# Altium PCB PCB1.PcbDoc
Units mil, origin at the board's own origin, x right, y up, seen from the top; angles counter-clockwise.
Board outline 3900 x 3400 mil, 2 copper layers (Top Layer, Bottom Layer); 10 components, 22 nets, 98 pads, 56 vias.
Unrouted connection lines stored in the file: 22.
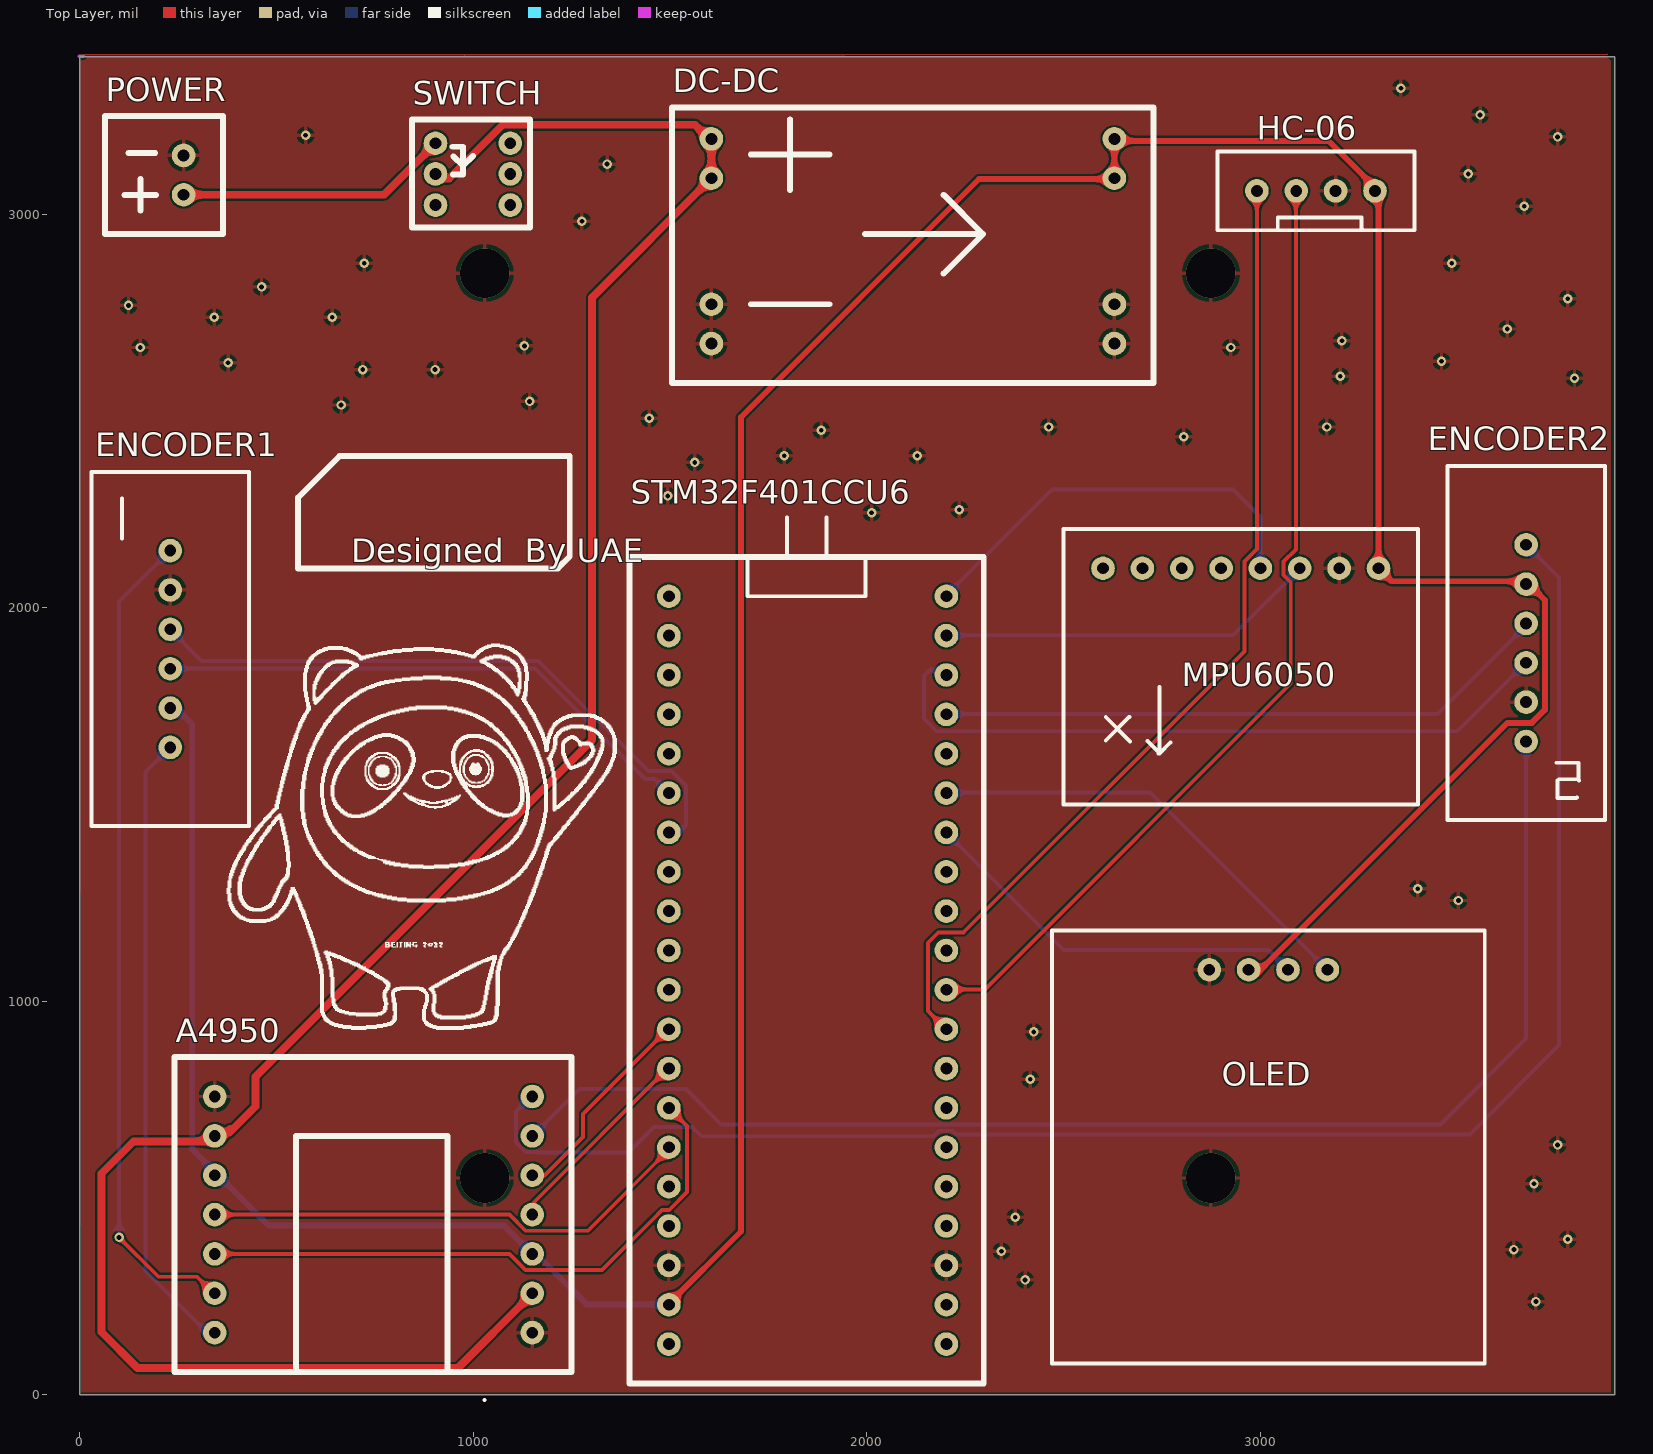
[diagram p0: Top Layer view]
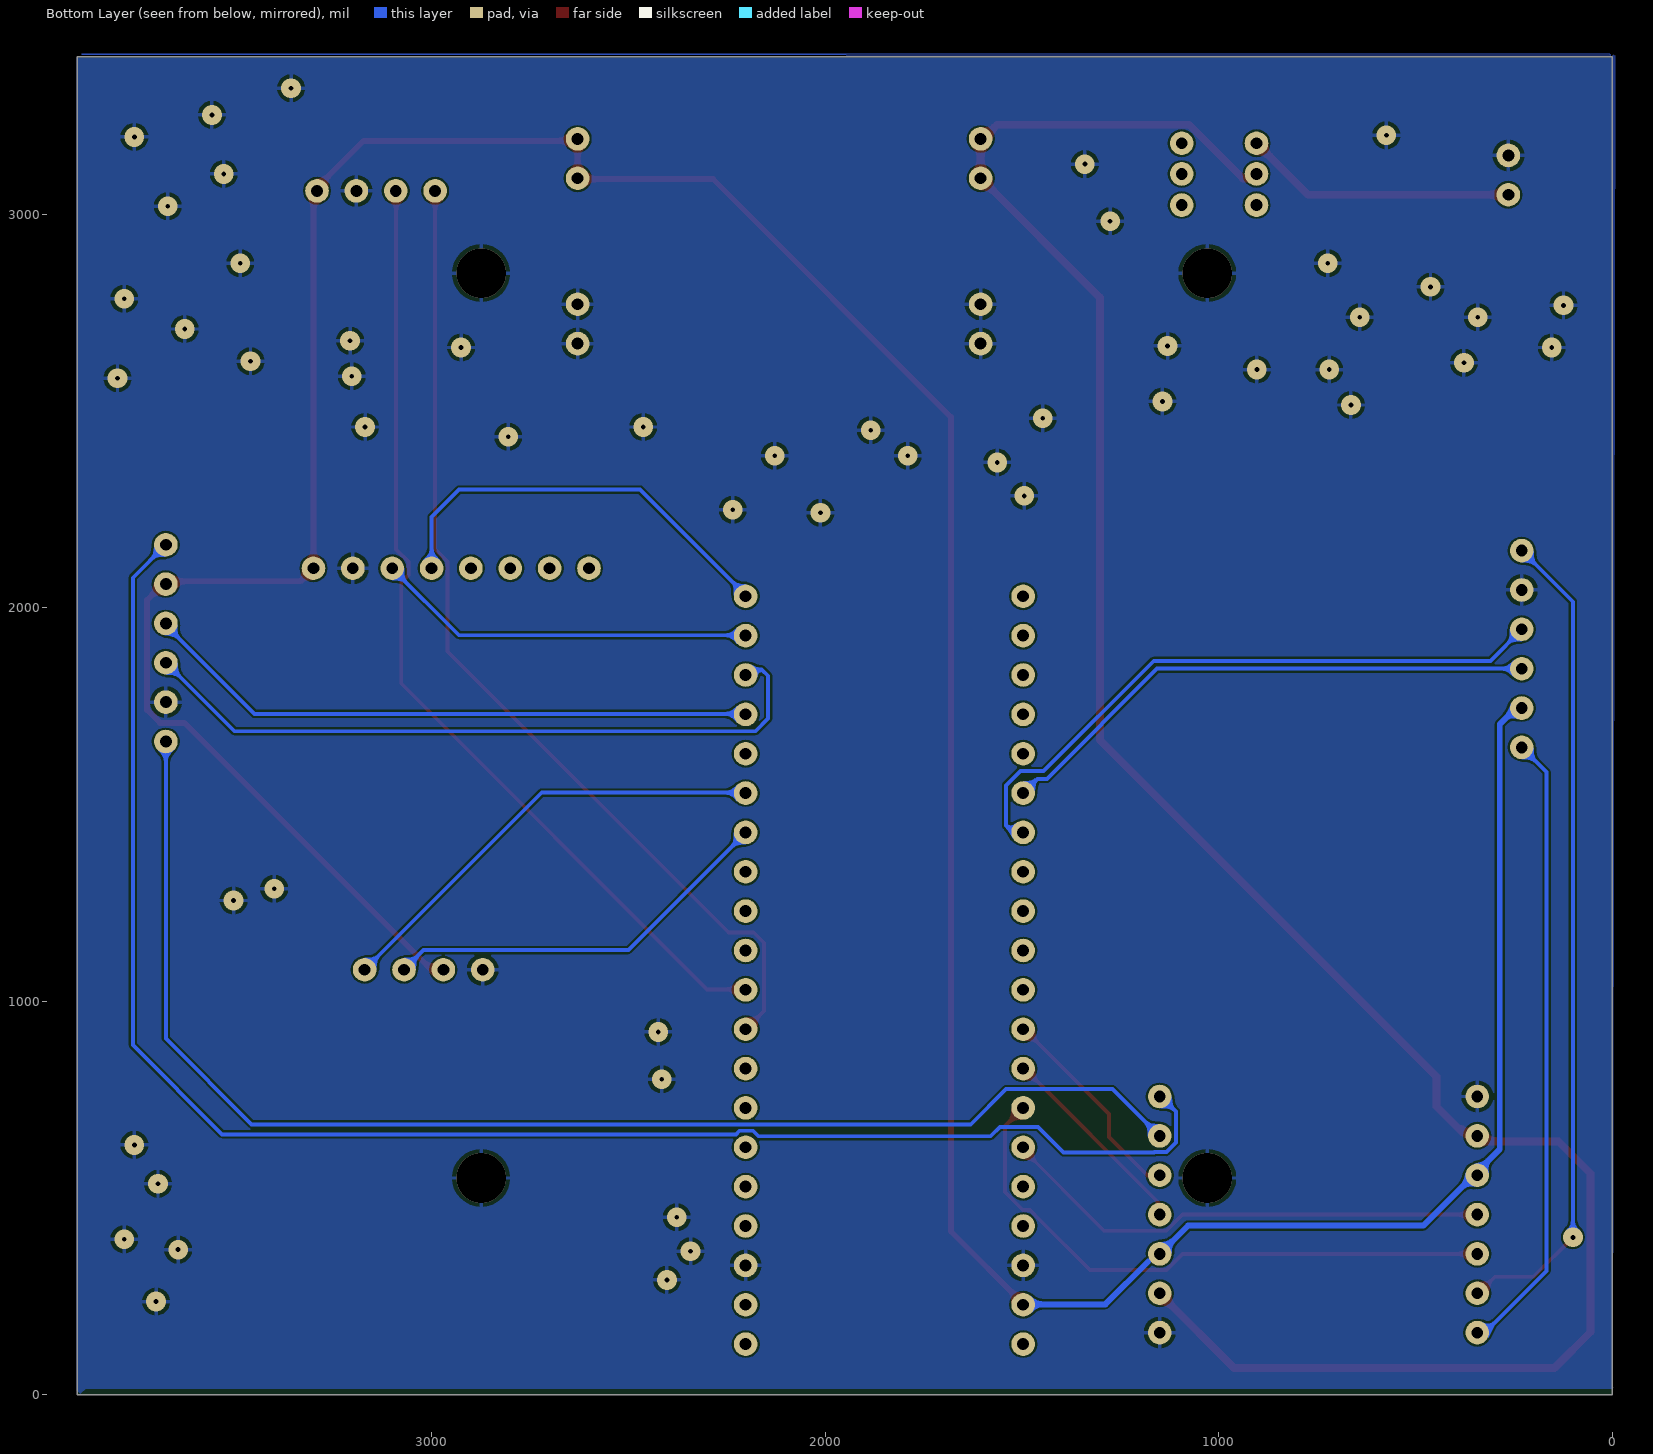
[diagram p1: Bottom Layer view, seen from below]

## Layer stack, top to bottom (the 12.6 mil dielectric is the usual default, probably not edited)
Top Solder: solder mask 0.4, Solder Resist, Dk 3.5
Top Layer: signal copper 1.4
Dielectric 1: dielectric 12.6, FR-4, Dk 4.8
Bottom Layer: signal copper 1.4
Bottom Solder: solder mask 0.4, Solder Resist, Dk 3.5

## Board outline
0,0 3900,0 3900,3400 0,3400

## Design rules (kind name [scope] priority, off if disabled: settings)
Clearance [All] p1: gap=6 ignorepadtopadclearanceinfootprint=FALSE except(5: Arc-Poly Track-Poly SMDPad-Poly THPad-Poly Via-Poly Fill-Poly Poly-Poly)
HoleSize [All] p1: absolutevalues=TRUE maxlimit=150 minlimit=1 maxpercent=80.000 minpercent=20.000
PolygonConnect [All] p1: connectstyle=Relief reliefconductorwidth=10 reliefentries=4 polygonreliefangle="90 Angle" airgapwidth=10
RoutingVias [All] p1: holewidth=12 width=24 viastyle="Through Hole" minholewidth=12 minwidth=10 maxholewidth=135 maxwidth=150
SilkToSolderMaskClearance [IsPad] p1: minsilkscreentomaskgap=4.9 clearancetoexposedcopper=TRUE
SolderMaskExpansion [All] p1: expansion=4
Width Width_3 [InNet('12V-IN')] p1: maxlimit=20 minlimit=10 preferedwidth=20
Width Width_1 [(InNet('12V') OR InNet('12V IN'))] p2: maxlimit=20 minlimit=10 preferedwidth=20
Width Width_2 [InNet('5V')] p3: maxlimit=15 minlimit=10 preferedwidth=15
Width [All] p4: maxlimit=10 minlimit=10 preferedwidth=10
28 further rules are at their usual default settings.

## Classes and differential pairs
component class Sheet1: DC-DC ENCODER1 ENCODER2 HC-06 MPU6050 OLED POWER STM32F401CCU6 SWITCH

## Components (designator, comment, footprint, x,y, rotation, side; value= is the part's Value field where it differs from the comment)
A4950 "A4950" A4950 1150,758 r180 top
DC-DC "DC-DC" DC-DC 1605,2671 r0 top
ENCODER1 "ENCODER1" ENCODER1 230,2145 r0 top
ENCODER2 "ENCODER2" ENCODER2 3675,1660 r180 top
HC-06 "HC-06" HC-06 2991,3059 r270 top
MPU6050 "MPU6050" MPU6050 3300,2100 r270 top
OLED "OLED" OLED 2870,1080 r0 top
POWER "POWER" POWER 264,3149 r0 top
STM32F401CCU6 "STM32F401CCU6" STM32F401CCU6 1497,129 r0 top
SWITCH "SWITCH" SIWITCH 994,3180 r0 top

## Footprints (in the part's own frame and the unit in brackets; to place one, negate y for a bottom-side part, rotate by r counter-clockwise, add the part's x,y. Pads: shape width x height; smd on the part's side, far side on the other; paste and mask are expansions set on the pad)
A4950 [mil]
  round 60 hole 30: 1(0,600) 2(0,500) 3(0,400) 4(0,300) 5(0,200) 6(0,100) 7(0,0) 8(807,600) 9(807,500) 10(807,400) 11(807,300) 12(807,200) 13(807,100) 14(807,0)
  silkscreen extent -100,-100 909,700
DC-DC [mil]
  round 60 hole 30: 1(0,0) 2(0,100) 3(0,420) 4(0,520) 5(1024,0) 6(1024,100) 7(1024,420) 8(1024,520)
  silkscreen extent -100,-100 1123,600
ENCODER1 [mil]
  round 60 hole 30: 1(0,0) 2(0,-100) 3(0,-200) 4(0,-300) 5(0,-400) 6(0,-500)
  silkscreen extent -200,-700 200,200
ENCODER2 [mil]
  round 60 hole 30: 1(0,0) 2(0,-100) 3(0,-200) 4(0,-300) 5(0,-400) 6(0,-500)
  silkscreen extent -200,-700 200,200
HC-06 [mil]
  round 60 hole 30: 1(0,0) 2(0,100) 3(0,200) 4(0,300)
  silkscreen extent -100,-100 100,400
MPU6050 [mil]
  round 60 hole 30: 1(0,0) 2(0,-100) 3(0,-200) 4(0,-300) 5(0,-400) 6(0,-500) 7(0,-600) 8(0,-700)
  silkscreen extent -100,-800 600,100
OLED [mil]
  round 60 hole 30: 1(0,0) 2(100,0) 3(200,0) 4(300,0)
  silkscreen extent -400,-1000 700,100
POWER [mil]
  round 60 hole 30: 1(0,0) 2(0,-100)
  silkscreen extent -200,-200 100,100
SIWITCH [mil]
  round 60 hole 30: 1(-90,0) 2(-90,-78) 3(-90,-157) 4(100,0) 5(100,-78) 6(100,-157)
  silkscreen extent -150,-214 150,60
STM32F401CCU6 [mil]
  round 60 hole 30: 1(0,1900) 2(0,1800) 3(0,1700) 4(0,1600) 5(0,1500) 6(0,1400) 7(0,1300) 8(0,1200) 9(0,1100) 10(0,1000) 11(0,900) 12(0,800) 13(0,700) 14(0,600) 15(0,500) 16(0,400) 17(0,300) 18(0,200) 19(0,100) 20(0,0) 21(705,1900) 22(705,1800) 23(705,1700) 24(705,1600) 25(705,1500) 26(705,1400) 27(705,1300) 28(705,1200) 29(705,1100) 30(705,1000) 31(705,900) 32(705,800) 33(705,700) 34(705,600) 35(705,500) 36(705,400) 37(705,300) 38(705,200) 39(705,100) 40(705,0)
  silkscreen extent -100,-100 800,2100

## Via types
v1: diameter 24/50 (per signal layer), hole 12, Top Layer to Bottom Layer, 52 vias
v2: diameter 126, hole 126, Top Layer to Bottom Layer, 4 vias

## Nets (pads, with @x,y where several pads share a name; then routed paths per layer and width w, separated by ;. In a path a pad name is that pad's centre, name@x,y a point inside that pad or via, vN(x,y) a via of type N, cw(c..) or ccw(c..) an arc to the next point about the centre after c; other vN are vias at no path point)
5V: A4950.3 A4950.12 DC-DC.7 DC-DC.8 ENCODER1.5 ENCODER2.5 HC-06.4 MPU6050.1 OLED.2 STM32F401CCU6.19 | length 9562.8
  Top Layer w15: STM32F401CCU6.19@1495,230 1680,415 1680,2484 2285,3089 2621,3089 DC-DC.7@2627,3083 ; DC-DC.7 DC-DC.8@2629,3186 ; DC-DC.8 DC-DC.8@2629,3186 ; OLED.2 3000,1080 3627.5,1707.5 3689.68,1707.5 3722.5,1740.32 3722.5,2019.68 3675,2067.18 3332.82,2067.18 MPU6050.1 3300,3059 3173,3186 DC-DC.8@2629,3186
  Bottom Layer w15: ENCODER1.5 245,1745 286,1704 286,624 480,430 1078,430 A4950.3 ; 1179,339 1288,230 STM32F401CCU6.19@1495,230
12V: A4950.2 A4950.13 DC-DC.3 DC-DC.4 SWITCH.2 | length 5788.4
  Top Layer w20: 380,666 447,733 447,809 1302,1664 1302,2788 DC-DC.3 DC-DC.4 ; 384,676 352,644 137,644 55,562 55,160 147,68 961,68 A4950.2@1143.5,250.5 ; SWITCH.2@895,3100 905.05,3089.95 937.95,3089.95 1075,3227 1563,3227 DC-DC.4@1596,3194
12V-IN: POWER.2 SWITCH.1 | length 694.3
  Top Layer w20: POWER.2 773,3049 SWITCH.1
AIN1: A4950.5 STM32F401CCU6.12 | length 503.1
  Top Layer w10: 1181,557 1279,655 1279,714 STM32F401CCU6.12@1495,930
AIN2: A4950.4 STM32F401CCU6.13 | length 524.4
  Top Layer w10: A4950.4@1144,451 1144,460 1153,469 1153,488 STM32F401CCU6.13@1495,830
AOUT1: A4950.9 ENCODER1.1 | length 2115.1
  Top Layer w10: v1(100,400) 200,300 298,300 329,269 A4950.9@362,269
  Bottom Layer w10: v1(100,400) 100,2015 ENCODER1.1
AOUT2: A4950.8 ENCODER1.6 | length 1587.5
  Bottom Layer w10: ENCODER1.6 167,1582 167,315 325,157 A4950.8@333,157
BIN1: A4950.10 STM32F401CCU6.14 | length 1548.1
  Top Layer w10: A4950.10 1092.02,358 1133.02,317 1327.02,317 1456,445.98 1480.02,470 1498,470 1543,515 1543,683 STM32F401CCU6.14 STM32F401CCU6.14@1513,729
BIN2: A4950.11 STM32F401CCU6.15 | length 1270.8
  Top Layer w10: A4950.11 1092.02,458 1133.02,417 1291,417 1503,629 STM32F401CCU6.15
BOUT1: A4950.6 ENCODER2.1 | length 3450.7
  Bottom Layer w10: A4950.6@1152,668 1161,668 1270,777 1540,777 1630,687 3457,687 3675,905 ENCODER2.1
BOUT2: A4950.7 ENCODER2.6 | length 4218.1
  Bottom Layer w10: A4950.7@1132,743 1109,720 1109,641.02 1133.02,617 1163,617 1164,616 1394,616 1459,681 1555.98,681 1579.98,657 2169.02,657 2183.02,671 2217.98,671 2226.98,662 3532,662 3759,889 3759,2076 ENCODER2.6
EN1A: ENCODER1.4 STM32F401CCU6.6 | length 1397.9
  Bottom Layer w10: ENCODER1.4 1156.72,1845 1436.72,1565 1461,1565 STM32F401CCU6.6
EN1B: ENCODER1.3 STM32F401CCU6.7 | length 1637
  Bottom Layer w10: ENCODER1.3 310,1865 1165,1865 1445,1585 1503.64,1585 1540,1548.64 1540,1446 1513,1419 STM32F401CCU6.7@1491,1419
EN2A: ENCODER2.4 STM32F401CCU6.24 | length 1573.2
  Bottom Layer w10: STM32F401CCU6.24@2200,1730 3450,1730 3675,1955 ENCODER2.4
EN2B: ENCODER2.3 STM32F401CCU6.23 | length 1790.5
  Bottom Layer w10: STM32F401CCU6.23@2200,1830 2188,1842 2160,1842 2145,1827 2145,1718 2177,1686 3501,1686 ENCODER2.3
GND: A4950.1 A4950.14 DC-DC.1 DC-DC.2 DC-DC.5 DC-DC.6 ENCODER1.2 ENCODER2.2 HC-06.3 MPU6050.2 OLED.1 POWER.1 STM32F401CCU6.18 STM32F401CCU6.38
  other v1: 3700,237 2402,292 2342,365 3644,369 3781,395 2377,451 3695,536 3755,635 2415,802 2424,922 3503,1256 3400,1286 2012,2241 2235,2249 1494,2284 1563,2369 1790,2386 2128,2386 2805,2434 1884,2451 2462,2459 3169,2459 1447,2481 664,2515 1143,2524 3798,2583 3203,2588 719,2605 903,2605 377,2622 3460,2626 154,2661 2925,2661 1130,2665 3207,2678 3627,2708 342,2738 642,2738 124,2768 3781,2785 462,2815 723,2875 3486,2875 1276,2982 3670,3020 3528,3102 1340,3127 3755,3196 574,3200 3558,3252 3357,3320
  other v2: 1029,551 2874,551 1029,2850 2874,2850
HC-05_RX: HC-06.1 STM32F401CCU6.32 | length 2531.2
  Top Layer w10: STM32F401CCU6.32@2200,930 2155,975 2155,1148.64 2181.36,1175 2245,1175 2959,1889 2959,2116.98 2991,2148.98 HC-06.1
HC-05_TX: HC-06.2 STM32F401CCU6.31 | length 2482.5
  Top Layer w10: STM32F401CCU6.31@2200,1030 2300,1030 3077,1807 3077,2065.02 3059,2083.02 3059,2116.98 3090,2147.98 3090,3052 HC-06.2@3077,3065
MPU_SCL: MPU6050.3 STM32F401CCU6.22 | length 970.4
  Bottom Layer w10: STM32F401CCU6.22@2200,1930 2930,1930 MPU6050.3
MPU_SDA: MPU6050.4 STM32F401CCU6.21 | length 1070.8
  Bottom Layer w10: STM32F401CCU6.21@2200,2030 2470,2300 2930,2300 3000,2230 MPU6050.4
OLED_SCL: OLED.3 STM32F401CCU6.27 | length 1015
  Bottom Layer w10: STM32F401CCU6.27@2200,1430 2500,1130 3020,1130 OLED.3
OLED_SDA: OLED.4 STM32F401CCU6.26 | length 1156.4
  Bottom Layer w10: STM32F401CCU6.26@2200,1530 2720,1530 OLED.4
pads on no net: MPU6050.5 MPU6050.6 MPU6050.7 MPU6050.8 STM32F401CCU6.1 STM32F401CCU6.2 STM32F401CCU6.3 STM32F401CCU6.4 STM32F401CCU6.5 STM32F401CCU6.8 STM32F401CCU6.9 STM32F401CCU6.10 STM32F401CCU6.11 STM32F401CCU6.16 STM32F401CCU6.17 STM32F401CCU6.20 STM32F401CCU6.25 STM32F401CCU6.28 STM32F401CCU6.29 STM32F401CCU6.30 STM32F401CCU6.33 STM32F401CCU6.34 STM32F401CCU6.35 STM32F401CCU6.36 STM32F401CCU6.37 STM32F401CCU6.39 STM32F401CCU6.40 SWITCH.3 SWITCH.4 SWITCH.5 SWITCH.6

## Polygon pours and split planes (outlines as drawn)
GND on Top Layer "Top Layer-GND" (solid, remove dead copper, pour order 56): -1,3401 3879,3401 3890,3390 3890,6 0,6 4,6
no net on Top Layer "Top Layer-No Net 5" (solid, pour order 28): 9,3401 14,3406 3882,3406
no net on Top Layer "Top Layer-No Net 1" (solid, pour order 22): 34,312
no net on Top Layer "Top Layer-No Net 2" (solid, pour order 20): 43,296
no net on Top Layer "Top Layer-No Net 3" (solid, pour order 18): -1,3401
no net on Top Layer "Top Layer-No Net" (solid, pour order 6): 219,1267
GND on Bottom Layer "Bottom Layer-GND" (solid, remove dead copper, pour order 54): -7,3409 5,3397 3901,3397 3901,12 3892,3 3879,16 2,16 -4,22 -1,22
no net on Bottom Layer "Bottom Layer-No Net" (solid, pour order 32): 4,3403 7,3406 3889,3406

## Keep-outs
Top Layer:
  lines w10: -1,3401 9,3401

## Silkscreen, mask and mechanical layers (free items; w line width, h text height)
Top Overlay:
  drawing of 3510 lines, arcs and shapes, not listed
  text "Designed  By UAE" at 690,2115 h60
Mechanical 1:
  lines w15: 0,0 0,900 0,3400 3900,3400 3900,0 0,0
